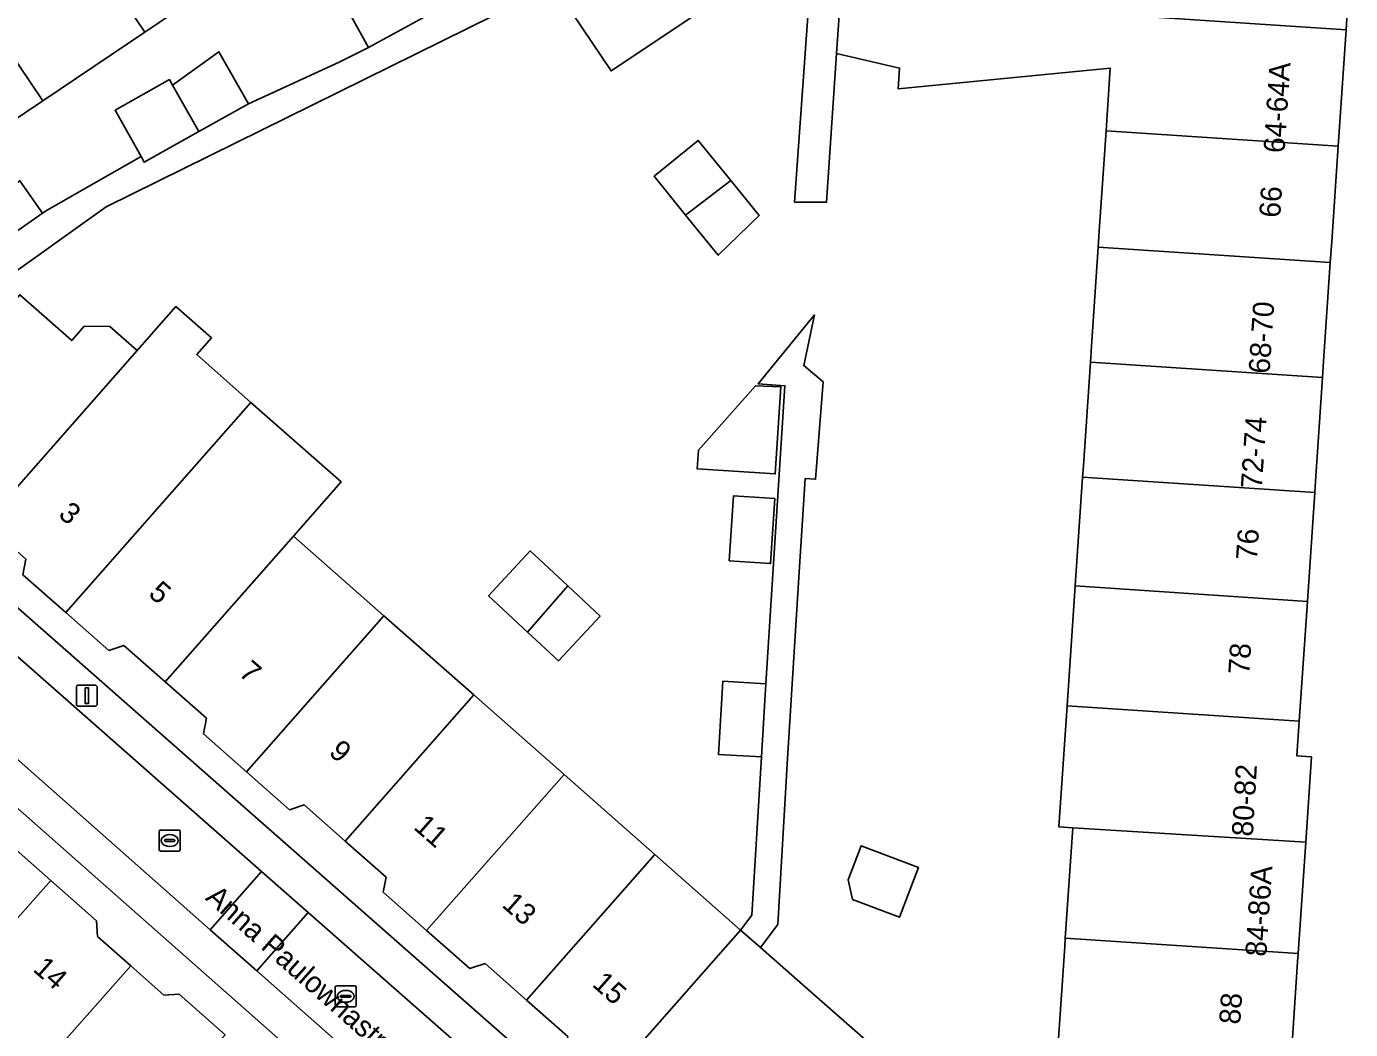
# Model space of a CAD drawing. Extents: x 159960 to 160866, y 382700 to 383354.
# Drawn here: x 160506.1 to 160568.9, y 382832 to 382879.6 of the extents above; entities that cross this region are included whole.
import ezdxf

# ---------------------------------------------------------------- set-up
doc = ezdxf.new("R2010")
doc.units = 0
for name, color, linetype in [('IMGEO_Erf', 7, 'Continuous'), ('IMGEO_Kolk', 7, 'Continuous'), ('IMGEO_Lichtmast', 7, 'Continuous'), ('IMGEO_Openbare_ruimte_label', 7, 'Continuous'), ('IMGEO_Pand', 7, 'Continuous'), ('IMGEO_Pand_nummerreeks', 7, 'Continuous'), ('IMGEO_Parkeervlak_open', 7, 'Continuous'), ('IMGEO_Rijbaan_lokaal_open', 7, 'Continuous'), ('IMGEO_Voetpad_open', 7, 'Continuous')]:
    doc.layers.add(name, color=color, linetype=linetype)

msp = doc.modelspace()

# ---------------------------------------------------------------- linework, layer by layer
at = {"layer": 'IMGEO_Erf'}
for points in [[(160555.046, 382830.875), (160555.388, 382835.941), (160555.415, 382836.339), (160555.768, 382841.56), (160555.117, 382841.604), (160555.505, 382847.351), (160555.89, 382853.036), (160556.239, 382858.199), (160556.274, 382858.722), (160556.607, 382863.649), (160556.658, 382864.407), (160556.975, 382869.099), (160557.042, 382870.093), (160557.348, 382874.613), (160557.549, 382877.583), (160547.49, 382876.598), (160547.557, 382877.585), (160544.567, 382878.278), (160544.094, 382871.236), (160542.574, 382871.236), (160543.703, 382887.115)], [(160542.541, 382883.247), (160533.87, 382877.453), (160531.13, 382881.556)], [(160516.566, 382882.547), (160511.744, 382879.299), (160506.908, 382876.042), (160502.102, 382872.804)], [(160530.736, 382881.292), (160509.915, 382871.014), (160504.629, 382867.246)], [(160505.827, 382872.25), (160506.9, 382870.709), (160507.114, 382870.858), (160509.414, 382872.164), (160511.571, 382873.395), (160510.339, 382875.593), (160512.916, 382877.04), (160513.068, 382876.774), (160515.267, 382878.359), (160516.667, 382875.901), (160520.974, 382877.863), (160522.369, 382878.563), (160520.976, 382881.101)], [(160505.819, 382866.841), (160508.283, 382864.67), (160508.881, 382865.349), (160510.094, 382865.335), (160511.385, 382864.198), (160513.223, 382866.284), (160514.916, 382864.791), (160514.219, 382864), (160516.785, 382861.739), (160521.07, 382857.963), (160518.81, 382855.398), (160523.096, 382851.622), (160527.361, 382847.865), (160531.64, 382844.097), (160535.945, 382840.304), (160540.016, 382836.718), (160540.552, 382837.429), (160541.001, 382844.923), (160538.963, 382845.045), (160539.171, 382848.515), (160541.209, 382848.393), (160542.119, 382862.528), (160540.854, 382862.61), (160543.52, 382865.882), (160543.013, 382863.485), (160543.928, 382862.713), (160543.572, 382858.092), (160543.084, 382858.124), (160542.797, 382853.681), (160542.245, 382844.848), (160541.774, 382836.979), (160540.954, 382835.892), (160543.366, 382833.768), (160546.598, 382830.922)]]:
    msp.add_lwpolyline(points, dxfattribs=at)
for points in [[(160537.407, 382870.616), (160535.909, 382872.463), (160538.001, 382874.161), (160539.551, 382872.251), (160540.891, 382870.599), (160538.954, 382868.71)], [(160541.655, 382858.348), (160537.953, 382858.587), (160538.011, 382859.479), (160540.715, 382862.526), (160541.921, 382862.467)], [(160539.476, 382854.22), (160539.675, 382857.302), (160541.634, 382857.175), (160541.435, 382854.093)], [(160529.902, 382850.848), (160528.056, 382852.568), (160530.038, 382854.694), (160531.823, 382853.031), (160533.351, 382851.608), (160531.37, 382849.48)], [(160545.323, 382838.171), (160545.118, 382839.099), (160545.734, 382840.714), (160548.449, 382839.678), (160547.55, 382837.321)]]:
    msp.add_lwpolyline(points, close=True, dxfattribs=at)
at = {"layer": 'IMGEO_Kolk'}
for p, q in [((160512.431, 382840.535), (160512.431, 382841.387)), ((160512.506, 382841.461), (160513.358, 382841.461)), ((160512.69, 382840.955), (160512.69, 382840.967)), ((160512.733, 382841.004), (160513.131, 382841.004)), ((160512.919, 382841.241), (160512.944, 382841.241)), ((160513.174, 382840.967), (160513.174, 382840.955)), ((160513.432, 382841.387), (160513.432, 382840.535)), ((160513.358, 382840.461), (160512.506, 382840.461)), ((160513.128, 382840.918), (160512.73, 382840.918)), ((160512.942, 382840.681), (160512.917, 382840.681)), ((160520.856, 382834.076), (160521.708, 382834.076)), ((160520.781, 382833.15), (160520.781, 382834.002)), ((160521.04, 382833.57), (160521.04, 382833.582)), ((160521.478, 382833.533), (160521.08, 382833.533)), ((160521.083, 382833.619), (160521.481, 382833.619)), ((160521.269, 382833.856), (160521.294, 382833.856)), ((160521.524, 382833.582), (160521.524, 382833.57)), ((160521.782, 382834.002), (160521.782, 382833.15)), ((160521.708, 382833.076), (160520.856, 382833.076)), ((160521.292, 382833.296), (160521.267, 382833.296))]:
    msp.add_line(p, q, dxfattribs=at)
for points in [[(160512.431, 382840.535), (160512.431, 382841.387)], [(160512.506, 382841.461), (160513.358, 382841.461)], [(160513.432, 382841.387), (160513.432, 382840.535)], [(160513.358, 382840.461), (160512.506, 382840.461)], [(160520.856, 382834.076), (160521.708, 382834.076)], [(160520.781, 382833.15), (160520.781, 382834.002)], [(160521.782, 382834.002), (160521.782, 382833.15)], [(160521.708, 382833.076), (160520.856, 382833.076)]]:
    msp.add_lwpolyline(points, dxfattribs=at)
for centre, radius, start, end in [((160512.508, 382841.385), 0.0765, 91.55205, 178.44795), ((160512.508, 382841.385), 0.0765, 91.55205, 178.44795), ((160512.73, 382840.964), 0.0403, 85.87752, 175.75265), ((160512.727, 382840.954), 0.0366, 178.93798, 274.71019), ((160513.131, 382840.961), 0.043, 264.86636, 352.45326), ((160513.135, 382840.966), 0.0386, 1.73085, 96.63898), ((160513.356, 382841.385), 0.0765, 1.55205, 88.44795), ((160513.356, 382841.385), 0.0765, 1.55205, 88.44795), ((160512.508, 382840.537), 0.0765, 181.55205, 268.44795), ((160512.508, 382840.537), 0.0765, 181.55205, 268.44795), ((160513.356, 382840.537), 0.0765, 271.55205, 358.44795), ((160513.356, 382840.537), 0.0765, 271.55205, 358.44795), ((160520.858, 382834), 0.0765, 91.55205, 178.44795), ((160520.858, 382834), 0.0765, 91.55205, 178.44795), ((160521.706, 382834), 0.0765, 1.55205, 88.44795), ((160521.706, 382834), 0.0765, 1.55205, 88.44795), ((160521.08, 382833.579), 0.0403, 85.87752, 175.75265), ((160521.077, 382833.569), 0.0366, 178.93798, 274.71019), ((160521.481, 382833.576), 0.043, 264.86636, 352.45326), ((160521.485, 382833.581), 0.0386, 1.73085, 96.63898), ((160520.858, 382833.152), 0.0765, 181.55205, 268.44795), ((160520.858, 382833.152), 0.0765, 181.55205, 268.44795), ((160521.706, 382833.152), 0.0765, 271.55205, 358.44795), ((160521.706, 382833.152), 0.0765, 271.55205, 358.44795)]:
    msp.add_arc(centre, radius, start, end, dxfattribs=at)
for centre, major_axis, ratio, start_param, end_param in [((160512.918, 382840.961), (-0.387, 0.002), 0.722429, 4.712389, 7.853982), ((160512.943, 382840.961), (-0.39, 0.002), 0.717154, 1.570796, 4.712389), ((160521.268, 382833.576), (-0.387, 0.002), 0.722429, 4.712389, 7.853982), ((160521.293, 382833.576), (-0.39, 0.002), 0.717154, 1.570796, 4.712389)]:
    msp.add_ellipse(centre, major_axis=major_axis, ratio=ratio, start_param=start_param, end_param=end_param, dxfattribs=at)
at = {"layer": 'IMGEO_Lichtmast'}
for p, q in [((160508.503, 382847.43), (160508.503, 382848.23)), ((160508.503, 382848.23), (160508.503, 382847.43)), ((160508.603, 382848.33), (160509.393, 382848.33)), ((160509.393, 382848.33), (160508.603, 382848.33)), ((160509.493, 382848.23), (160509.493, 382847.43)), ((160509.493, 382847.43), (160509.493, 382848.23)), ((160509.393, 382847.33), (160508.603, 382847.33)), ((160508.603, 382847.33), (160509.393, 382847.33))]:
    msp.add_line(p, q, dxfattribs=at)
msp.add_lwpolyline([(160508.923, 382848.205), (160509.073, 382848.205), (160509.073, 382847.455), (160508.923, 382847.455), (160508.923, 382848.205)], dxfattribs=at)
for centre, start, end in [((160508.603, 382848.23), 90, 180), ((160508.603, 382848.23), 90, 180), ((160509.393, 382848.23), 0, 90), ((160509.393, 382848.23), 360, 90), ((160508.603, 382847.43), 180, 270), ((160508.603, 382847.43), 180, 270), ((160509.393, 382847.43), 270, 0), ((160509.393, 382847.43), 270, 0)]:
    msp.add_arc(centre, 0.1, start, end, dxfattribs=at)
at = {"layer": 'IMGEO_Pand'}
for points in [[(160509.479, 382893.069), (160507.455, 382891.705), (160507.265, 382890.73), (160505.05, 382889.238), (160511.744, 382879.299), (160516.566, 382882.547)], [(160506.908, 382876.042), (160511.744, 382879.299), (160505.05, 382889.238), (160502.834, 382887.745), (160501.72, 382887.963), (160500, 382886.806), (160499.765, 382886.648), (160500, 382886.299)], [(160541.609, 382888.558), (160531.13, 382881.556), (160533.87, 382877.453), (160542.541, 382883.247), (160543.124, 382886.291)], [(160506.908, 382876.042), (160500, 382886.299), (160499.765, 382886.648), (160497.812, 382885.331), (160497.635, 382884.424), (160495.325, 382882.868), (160500, 382875.926), (160502.102, 382872.804)], [(160557.721, 382880.127), (160568.735, 382879.396), (160568.825, 382880.731), (160569.108, 382884.914), (160558.093, 382885.645), (160557.811, 382881.464)], [(160523.346, 382882.401), (160520.976, 382881.101), (160522.369, 382878.563), (160524.969, 382879.99)], [(160557.348, 382874.613), (160568.361, 382873.881), (160568.44, 382875.045), (160568.735, 382879.396), (160557.721, 382880.127), (160544.75, 382881.002), (160544.567, 382878.278), (160547.557, 382877.585), (160547.49, 382876.598), (160557.549, 382877.583)], [(160513.068, 382876.774), (160514.316, 382874.583), (160516.667, 382875.901), (160515.267, 382878.359)], [(160513.068, 382876.774), (160512.916, 382877.04), (160510.339, 382875.593), (160511.571, 382873.395), (160511.721, 382873.127), (160514.316, 382874.583)], [(160557.348, 382874.613), (160557.042, 382870.093), (160556.975, 382869.099), (160567.989, 382868.367), (160568.056, 382869.36), (160568.361, 382873.881)], [(160539.551, 382872.251), (160538.001, 382874.161), (160535.909, 382872.463), (160537.407, 382870.616)], [(160503.546, 382870.661), (160504.595, 382869.103), (160506.9, 382870.709), (160505.827, 382872.25)], [(160539.551, 382872.251), (160537.407, 382870.616), (160538.954, 382868.71), (160540.891, 382870.599)], [(160567.621, 382862.917), (160567.672, 382863.674), (160567.989, 382868.367), (160556.975, 382869.099), (160556.658, 382864.407), (160556.607, 382863.649)], [(160504.171, 382856.013), (160511.385, 382864.198), (160510.094, 382865.335), (160508.881, 382865.349), (160508.283, 382864.67), (160505.819, 382866.841), (160505.499, 382866.479), (160504.629, 382867.246), (160496.73, 382861.746), (160499.303, 382859.447), (160500, 382858.814), (160501.513, 382857.48), (160502.231, 382857.722)], [(160516.785, 382861.739), (160514.219, 382864), (160514.916, 382864.791), (160513.223, 382866.284), (160511.385, 382864.198), (160504.171, 382856.013), (160506.111, 382854.304), (160505.962, 382853.562), (160507.998, 382851.769)], [(160567.621, 382862.917), (160556.607, 382863.649), (160556.274, 382858.722), (160556.239, 382858.199), (160567.253, 382857.467), (160567.288, 382857.989)], [(160540.715, 382862.526), (160538.011, 382859.479), (160537.953, 382858.587), (160541.655, 382858.348), (160541.921, 382862.467)], [(160516.785, 382861.739), (160507.998, 382851.769), (160510.036, 382849.974), (160510.753, 382850.216), (160512.718, 382848.485), (160518.81, 382855.398), (160521.07, 382857.963)], [(160566.903, 382852.303), (160567.253, 382857.467), (160556.239, 382858.199), (160555.89, 382853.036)], [(160539.476, 382854.22), (160541.435, 382854.093), (160541.634, 382857.175), (160539.675, 382857.302)], [(160516.573, 382844.221), (160523.096, 382851.622), (160518.81, 382855.398), (160512.718, 382848.485), (160514.679, 382846.757), (160514.53, 382846.02)], [(160531.823, 382853.031), (160530.038, 382854.694), (160528.056, 382852.568), (160529.902, 382850.848)], [(160533.351, 382851.608), (160531.823, 382853.031), (160529.902, 382850.848), (160531.37, 382849.48)], [(160566.903, 382852.303), (160555.89, 382853.036), (160555.505, 382847.351), (160566.519, 382846.618)], [(160521.254, 382840.936), (160527.361, 382847.865), (160523.096, 382851.622), (160516.573, 382844.221), (160518.615, 382842.422), (160519.305, 382842.654)], [(160539.171, 382848.515), (160538.963, 382845.045), (160541.001, 382844.923), (160541.209, 382848.393)], [(160521.254, 382840.936), (160523.205, 382839.218), (160523.063, 382838.509), (160525.119, 382836.698), (160531.64, 382844.097), (160527.361, 382847.865)], [(160555.768, 382841.56), (160566.821, 382840.891), (160567.094, 382844.929), (160566.408, 382844.975), (160566.519, 382846.618), (160555.505, 382847.351), (160555.117, 382841.604)], [(160525.119, 382836.698), (160527.173, 382834.889), (160527.893, 382835.131), (160529.86, 382833.399), (160535.945, 382840.304), (160531.64, 382844.097)], [(160502.839, 382842.336), (160500, 382839.133), (160495.769, 382834.359), (160499.883, 382830.712), (160500, 382830.844), (160507.29, 382839.07), (160505.115, 382840.993), (160504.405, 382840.95)], [(160566.821, 382840.891), (160555.768, 382841.56), (160555.415, 382836.339), (160566.464, 382835.605)], [(160545.118, 382839.099), (160545.323, 382838.171), (160547.55, 382837.321), (160548.449, 382839.678), (160545.734, 382840.714)], [(160540.016, 382836.718), (160535.945, 382840.304), (160529.86, 382833.399), (160531.823, 382831.669), (160531.686, 382830.986), (160533.258, 382829.602), (160533.95, 382829.834)], [(160504.015, 382827.051), (160511.082, 382835.025), (160509.508, 382836.417), (160509.463, 382837.147), (160507.29, 382839.07), (160500, 382830.844), (160499.883, 382830.712), (160500, 382830.609)], [(160546.598, 382830.922), (160543.366, 382833.768), (160540.954, 382835.892), (160540.016, 382836.718), (160533.95, 382829.834), (160536.694, 382827.417), (160536.238, 382826.899), (160540.122, 382823.477), (160540.224, 382823.593), (160543.428, 382827.229), (160545.289, 382829.397)], [(160555.415, 382836.339), (160555.388, 382835.941), (160555.046, 382830.875), (160566.095, 382830.14), (160566.437, 382835.206), (160566.464, 382835.605)], [(160508.147, 382823.389), (160515.562, 382831.755), (160513.385, 382833.68), (160512.653, 382833.636), (160511.082, 382835.025), (160504.015, 382827.051)]]:
    msp.add_lwpolyline(points, close=True, dxfattribs=at)
at = {"layer": 'IMGEO_Parkeervlak_open'}
for points in [[(160517.061, 382834.787), (160514.857, 382836.733), (160500, 382849.852), (160491.055, 382857.75), (160490.411, 382858.318), (160488.994, 382859.57), (160488.216, 382860.257), (160484.747, 382863.32), (160482.022, 382867.417), (160480.582, 382866.475), (160483.486, 382862.118), (160536.081, 382815.679), (160553.999, 382800.386), (160558.536, 382800.02), (160558.688, 382801.778), (160554.12, 382802.065), (160543.495, 382811.446), (160542.999, 382811.884), (160542.301, 382811.048), (160540.727, 382812.411), (160541.439, 382813.262), (160541.291, 382813.393)], [(160495.05, 382861.37), (160494.549, 382861.818), (160493.381, 382860.512), (160493.445, 382860.456), (160493.877, 382860.076), (160500, 382854.692), (160517.292, 382839.486), (160519.501, 382837.545), (160543.733, 382816.237), (160543.808, 382816.171), (160544.522, 382816.983), (160546.068, 382815.591), (160545.373, 382814.795), (160545.941, 382814.296), (160550.918, 382809.919), (160552.075, 382811.222)]]:
    msp.add_lwpolyline(points, close=True, dxfattribs=at)
at = {"layer": 'IMGEO_Rijbaan_lokaal_open'}
for points in [[(160500, 382854.692), (160493.877, 382860.076), (160493.445, 382860.456), (160493.381, 382860.512), (160492.789, 382861.032), (160490.411, 382858.318), (160491.055, 382857.75), (160500, 382849.852), (160514.857, 382836.733), (160517.292, 382839.486)], [(160519.501, 382837.545), (160517.292, 382839.486), (160514.857, 382836.733), (160517.061, 382834.787)], [(160519.501, 382837.545), (160517.061, 382834.787), (160541.291, 382813.393), (160543.733, 382816.237)]]:
    msp.add_lwpolyline(points, close=True, dxfattribs=at)
at = {"layer": 'IMGEO_Voetpad_open'}
for points in [[(160543.703, 382887.115), (160542.574, 382871.236), (160544.094, 382871.236), (160544.567, 382878.278), (160544.75, 382881.002)], [(160504.629, 382867.246), (160509.915, 382871.014), (160530.736, 382881.292)], [(160568.825, 382880.731), (160568.735, 382879.396), (160568.44, 382875.045), (160568.361, 382873.881), (160568.056, 382869.36), (160567.989, 382868.367), (160567.672, 382863.674), (160567.621, 382862.917), (160567.288, 382857.989), (160567.253, 382857.467), (160566.903, 382852.303), (160566.519, 382846.618), (160566.408, 382844.975), (160567.094, 382844.929), (160566.821, 382840.891), (160566.464, 382835.605), (160566.437, 382835.206), (160566.095, 382830.14)], [(160524.969, 382879.99), (160522.369, 382878.563), (160520.974, 382877.863), (160516.667, 382875.901), (160514.316, 382874.583), (160511.721, 382873.127), (160511.571, 382873.395), (160509.414, 382872.164), (160507.114, 382870.858), (160506.9, 382870.709), (160504.595, 382869.103)], [(160536.081, 382815.679), (160483.486, 382862.118)], [(160495.05, 382861.37), (160552.075, 382811.222)], [(160531.823, 382831.669), (160529.86, 382833.399), (160527.893, 382835.131), (160527.173, 382834.889), (160525.119, 382836.698), (160523.063, 382838.509), (160523.205, 382839.218), (160521.254, 382840.936), (160519.305, 382842.654), (160518.615, 382842.422), (160516.573, 382844.221), (160514.53, 382846.02), (160514.679, 382846.757), (160512.718, 382848.485), (160510.753, 382850.216), (160510.036, 382849.974), (160507.998, 382851.769), (160505.962, 382853.562)], [(160505.115, 382840.993), (160507.29, 382839.07), (160509.463, 382837.147), (160509.508, 382836.417), (160511.082, 382835.025), (160512.653, 382833.636), (160513.385, 382833.68), (160515.562, 382831.755)]]:
    msp.add_lwpolyline(points, dxfattribs=at)
msp.add_lwpolyline([(160543.52, 382865.882), (160540.854, 382862.61), (160542.119, 382862.528), (160541.209, 382848.393), (160541.001, 382844.923), (160540.552, 382837.429), (160540.016, 382836.718), (160540.954, 382835.892), (160541.774, 382836.979), (160542.245, 382844.848), (160542.797, 382853.681), (160543.084, 382858.124), (160543.572, 382858.092), (160543.928, 382862.713), (160543.013, 382863.485)], close=True, dxfattribs=at)

# ---------------------------------------------------------------- texts
at = {"layer": 'IMGEO_Openbare_ruimte_label'}
msp.add_text('Anna Paulownastraat', height=1, rotation=318.56623, dxfattribs=at).set_placement((160514.581, 382838.184))
at = {"layer": 'IMGEO_Pand_nummerreeks'}
for s, rotation, p in [('64-64A', 86.13178, (160565.812, 382873.537)), ('66', 86.13213, (160565.606, 382870.473)), ('68-70', 86.1356, (160565.106, 382863.076)), ('72-74', 86.1356, (160564.737, 382857.622)), ('3', 318.67347, (160507.597, 382856.363)), ('76', 86.12641, (160564.508, 382854.234)), ('5', 318.67347, (160511.875, 382852.6)), ('78', 86.13576, (160564.141, 382848.812)), ('7', 318.67347, (160516.154, 382848.838)), ('9', 318.67347, (160520.432, 382845.076)), ('80-82', 86.65007, (160564.311, 382841.134)), ('11', 318.67347, (160524.452, 382841.543)), ('84-86A', 86.13847, (160564.949, 382835.435)), ('13', 318.67347, (160528.644, 382837.855)), ('14', 318.47658, (160506.399, 382834.804)), ('15', 318.67347, (160532.923, 382834.093)), ('88', 86.13226, (160563.71, 382832.224))]:
    msp.add_text(s, height=1, rotation=rotation, dxfattribs=at).set_placement(p)

doc.saveas('drawing.dxf')
